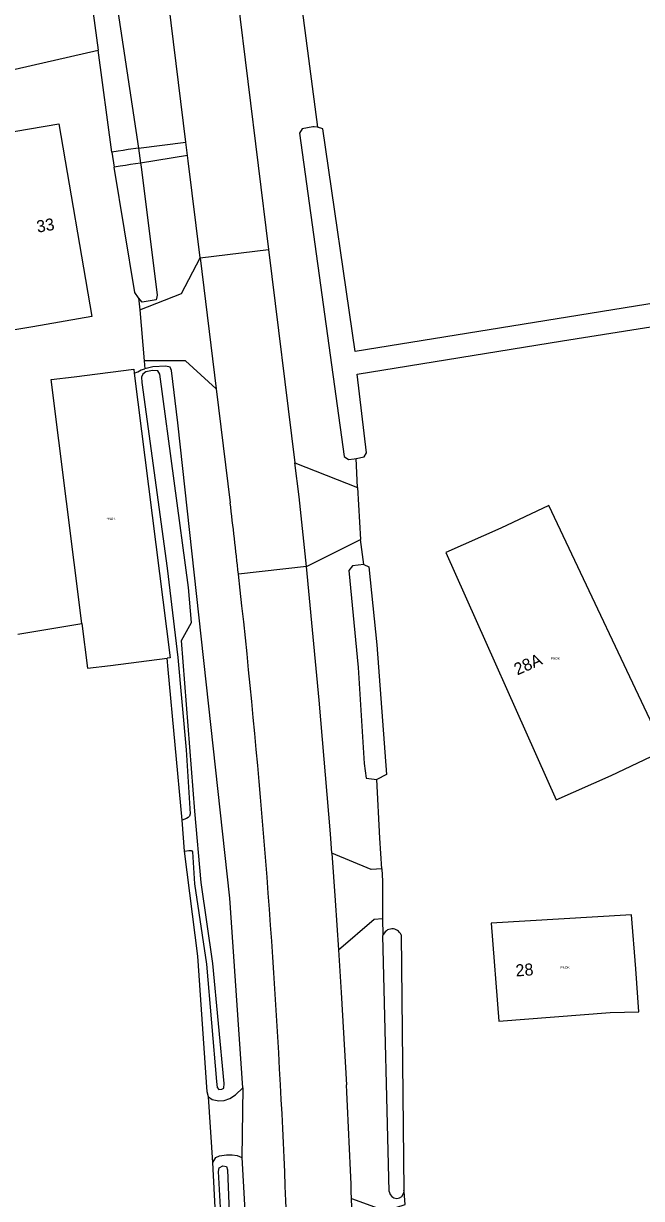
# Model space of a CAD drawing. Extents: x 134297 to 137000, y 403500 to 406000.
# Drawn here: x 135031.2 to 135082.6, y 403740.5 to 403838.3 of the extents above; entities that cross this region are included whole.
import ezdxf

# ---------------------------------------------------------------- set-up
doc = ezdxf.new("R2010")
doc.units = 0
for name, color, linetype in [('gg-anno-huisnummerreeks BGT', 7, 'Continuous'), ('gx-grn-maaiveld', 7, 'Continuous'), ('kenmerkpunt-x pandkandidaat', 7, 'Continuous')]:
    doc.layers.add(name, color=color, linetype=linetype)

msp = doc.modelspace()

# ---------------------------------------------------------------- linework, layer by layer
at = {"layer": 'gx-grn-maaiveld'}
for p, q in [((135050.637, 403867.996), (135055.651, 403829.705)), ((135046.027, 403864.51), (135051.573, 403819.537)), ((135038.545, 403827.639), (135037.401, 403836.115)), ((135040.75, 403827.964), (135044.697, 403828.461)), ((135044.834, 403827.342), (135044.697, 403828.461)), ((135038.545, 403827.639), (135038.729, 403826.391)), ((135040.75, 403827.964), (135040.934, 403826.716)), ((135044.834, 403827.342), (135040.934, 403826.716)), ((135045.879, 403818.835), (135051.573, 403819.537)), ((135045.879, 403818.835), (135047.219, 403807.929)), ((135051.573, 403819.537), (135053.764, 403801.773)), ((135040.766, 403815.515), (135040.853, 403814.51)), ((135040.853, 403814.51), (135041.221, 403810.247)), ((135041.221, 403810.247), (135041.278, 403809.586)), ((135047.219, 403807.929), (135048.383, 403798.45)), ((135058.984, 403799.713), (135058.864, 403802.117)), ((135053.764, 403801.773), (135058.984, 403799.713)), ((135058.984, 403799.713), (135059.229, 403795.393)), ((135054.731, 403793.131), (135059.229, 403795.393)), ((135059.495, 403793.292), (135059.229, 403795.393)), ((135054.731, 403793.131), (135049.073, 403792.499)), ((135030.725, 403787.501), (135036.051, 403788.394)), ((135044.585, 403769.445), (135044.381, 403772.032)), ((135061.062, 403763.822), (135061.096, 403762.426)), ((135061.62, 403741.092), (135061.096, 403762.426)), ((135062.611, 403762.466), (135062.839, 403741.19)), ((135049.431, 403749.744), (135049.344, 403743.941)), ((135046.951, 403743.53), (135046.586, 403748.987)), ((135058.749, 403733.177), (135058.487, 403740.522)), ((135062.847, 403741.108), (135062.839, 403741.19)), ((135062.945, 403740.034), (135062.847, 403741.108))]:
    msp.add_line(p, q, dxfattribs=at)
for points in [[(135044.697, 403828.461), (135040.617, 403861.674), (135040.452, 403863.017)], [(135034.322, 403861.058), (135034.68, 403861.286), (135035.061, 403861.33), (135035.939, 403861.431), (135036.251, 403861.105), (135037.771, 403847.847), (135040.75, 403827.964)], [(135034.322, 403861.058), (135036.984, 403839.201), (135037.401, 403836.115)], [(135058.864, 403802.117), (135059.543, 403802.273), (135059.72, 403802.602), (135058.943, 403809.138), (135076.035, 403811.931), (135104.008, 403816.363), (135100.594, 403852.945), (135098.701, 403852.71), (135101.655, 403817.983), (135058.786, 403811.039), (135056.084, 403829.568), (135055.651, 403829.705)], [(134969.991, 403817.24), (134980.913, 403823.2), (135037.401, 403836.115)], [(135029.202, 403829.148), (135034.121, 403830.001), (135036.882, 403813.939), (135031.951, 403813.089), (135028.965, 403812.577), (135026.771, 403825.331), (135023.051, 403824.691), (135017.656, 403823.763), (135019.349, 403813.916), (134995.634, 403809.838), (134993.388, 403822.899), (135022.498, 403827.905), (135029.202, 403829.148)], [(135055.651, 403829.705), (135055.382, 403829.734), (135055.253, 403829.748), (135054.367, 403829.565), (135054.138, 403829.224), (135057.862, 403802.297), (135058.221, 403802.042), (135058.698, 403802.098), (135058.864, 403802.117)], [(135040.75, 403827.964), (135039.904, 403827.84), (135039.485, 403827.778), (135039.066, 403827.716), (135038.545, 403827.639)], [(135040.934, 403826.716), (135040.08, 403826.59), (135039.661, 403826.528), (135039.242, 403826.466), (135038.729, 403826.391)], [(135040.934, 403826.716), (135040.972, 403826.407), (135042.302, 403815.732), (135042.277, 403815.576), (135042.237, 403815.327), (135041.046, 403815.13), (135040.766, 403815.515)], [(135045.879, 403818.835), (135044.887, 403826.91), (135044.834, 403827.342)], [(135040.766, 403815.515), (135040.444, 403815.938), (135038.729, 403826.391)], [(135040.853, 403814.51), (135044.338, 403815.858), (135045.879, 403818.835)], [(135047.219, 403807.929), (135044.671, 403810.245), (135041.221, 403810.247)], [(135049.431, 403749.744), (135048.352, 403765.521), (135044.014, 403805.103), (135043.502, 403809.454), (135043.386, 403809.72), (135043.023, 403809.812), (135041.956, 403809.764), (135041.278, 403809.586)], [(135036.051, 403788.394), (135033.491, 403808.702), (135035.4, 403808.939), (135040.361, 403809.568), (135040.405, 403809.22)], [(135040.405, 403809.22), (135040.701, 403809.335), (135040.986, 403809.509), (135041.278, 403809.586)], [(135040.405, 403809.22), (135043.391, 403785.53), (135043.132, 403785.497)], [(135044.585, 403769.445), (135044.953, 403769.499), (135045.152, 403769.481), (135045.235, 403769.373), (135045.405, 403766.72), (135046.404, 403760.034), (135047.25, 403750.273), (135047.307, 403749.773), (135047.449, 403749.593), (135047.694, 403749.622), (135047.865, 403749.72), (135047.874, 403750.097), (135046.933, 403760.099), (135045.972, 403766.824), (135045.434, 403772.78), (135044.329, 403786.972), (135045.175, 403788.471), (135044.925, 403791.392), (135042.542, 403809.146), (135042.369, 403809.415), (135041.908, 403809.453), (135041.37, 403809.338), (135041.101, 403809.146), (135040.996, 403808.901), (135041.024, 403808.454), (135043.138, 403793.006), (135044.022, 403785.551), (135044.714, 403777.865), (135045.04, 403772.559), (135044.993, 403772.361), (135044.885, 403772.253), (135044.749, 403772.171), (135044.381, 403772.032)], [(135054.731, 403793.131), (135054.113, 403798.941), (135053.764, 403801.773)], [(135075.501, 403773.719), (135080.071, 403775.75), (135084.517, 403777.854), (135074.897, 403798.205), (135070.911, 403796.319), (135066.34, 403794.29), (135075.501, 403773.719)], [(135059.495, 403793.292), (135059.032, 403793.247), (135058.568, 403793.201), (135058.246, 403792.805), (135059.023, 403784.732), (135059.54, 403776.727), (135059.688, 403775.511), (135060.583, 403775.394)], [(135059.495, 403793.292), (135059.913, 403793.1), (135060.586, 403786.627), (135061.4, 403775.822), (135060.583, 403775.394)], [(135056.84, 403769.273), (135056.722, 403770.893), (135055.8, 403782.019), (135054.731, 403793.131)], [(135036.051, 403788.394), (135036.521, 403784.664), (135038.43, 403784.9), (135043.132, 403785.497)], [(135044.381, 403772.032), (135043.218, 403784.575), (135043.132, 403785.497)], [(135060.988, 403767.978), (135060.824, 403770.523), (135060.583, 403775.394)], [(135046.586, 403748.987), (135046.471, 403749.41), (135045.702, 403760.708), (135044.585, 403769.445)], [(135060.988, 403767.978), (135060.108, 403767.921), (135056.84, 403769.273)], [(135056.84, 403769.273), (135057.126, 403765.344), (135057.394, 403761.234)], [(135060.988, 403767.978), (135061.055, 403766.931), (135061.062, 403763.822)], [(135057.394, 403761.234), (135060.374, 403763.778), (135061.062, 403763.822)], [(135082.131, 403759.649), (135081.77, 403764.129), (135070.09, 403763.44), (135070.732, 403755.279), (135080.014, 403756.008), (135082.377, 403756.071), (135082.131, 403759.649)], [(135057.394, 403761.234), (135057.626, 403757.663), (135058.055, 403749.978)], [(135046.586, 403748.987), (135046.894, 403748.757), (135047.432, 403748.641), (135047.874, 403748.68), (135048.354, 403748.853), (135048.815, 403749.16), (135049.431, 403749.744)], [(135046.951, 403743.53), (135047.182, 403743.934), (135047.489, 403744.087), (135048.066, 403744.164), (135048.546, 403744.164), (135048.969, 403744.107), (135049.344, 403743.941)], [(135048.269, 403661.402), (135048.508, 403662.925), (135048.642, 403669.65), (135048.181, 403697.127), (135047.874, 403723.105), (135047.374, 403734.903), (135046.951, 403743.53)], [(135049.344, 403743.941), (135050.32, 403726.679), (135050.621, 403703.438), (135051.004, 403669.814), (135050.927, 403662.756), (135050.536, 403661.631), (135049.892, 403661.131), (135049.321, 403661.012), (135048.538, 403661.138), (135048.269, 403661.402)], [(135048.974, 403672.412), (135049.127, 403683.365), (135048.935, 403692.511), (135048.705, 403705.73), (135048.666, 403713.301), (135048.32, 403722.14), (135047.975, 403732.784), (135047.398, 403742.757), (135047.475, 403743.083), (135047.782, 403743.237), (135048.071, 403743.18), (135048.148, 403742.911), (135048.743, 403728.058), (135049.051, 403716.106), (135049.32, 403705.807), (135049.339, 403703.136), (135049.32, 403688.706)], [(135058.487, 403740.522), (135061.296, 403739.486), (135062.945, 403740.034)]]:
    msp.add_lwpolyline(points, dxfattribs=at)
for centre, radius, start, end in [((134308.168, 403709.609), 745.528, 6.383528, 6.843944), ((134324.32, 403711.474), 729.268, 3.026474, 6.379028), ((135061.861, 403762.159), 0.81, 22.26858, 160.75623), ((134325.105, 403711.44), 728.486, 359.994312, 3.032345), ((134199.732, 403706.027), 859.448, 2.300229, 2.931281), ((135062.233, 403741.145), 0.615, 184.95696, 356.53722)]:
    msp.add_arc(centre, radius, start, end, dxfattribs=at)

# ---------------------------------------------------------------- texts
at = {"layer": 'gg-anno-huisnummerreeks BGT'}
for s, rotation, p in [('33', 9.7, (135032.356, 403820.922)), ('28A', 24, (135072.272, 403784.06)), ('28', 4.5, (135072.168, 403758.997))]:
    msp.add_text(s, height=1, rotation=rotation, dxfattribs=at).set_placement(p)
at = {"layer": 'kenmerkpunt-x pandkandidaat'}
for p in [(135038.07, 403797.013), (135075.058, 403785.381), (135075.863, 403759.657)]:
    msp.add_text('PNDK', height=0.2, dxfattribs=at).set_placement(p)

doc.saveas('drawing.dxf')
